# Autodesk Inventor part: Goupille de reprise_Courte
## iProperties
Shininess: 64.0
Length Units: 11269
Angle Units: 11279
Time Units: 11290
Mass Units: 11283
Length Display Precision: 3
Angle Display Precision: 2
Compacted: True
Part Number: Goupille de reprise_Courte
Document SubType Name: Modeling
Created: 2006-01
Material: Par défaut
Designer: riri
Density: 0.0
Volumn: 0.0
Area: 0.0
PropertySet Name: Model Information
Control State: 0
Master: False
Checked Out: False
Author: riri
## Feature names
1. Base1
